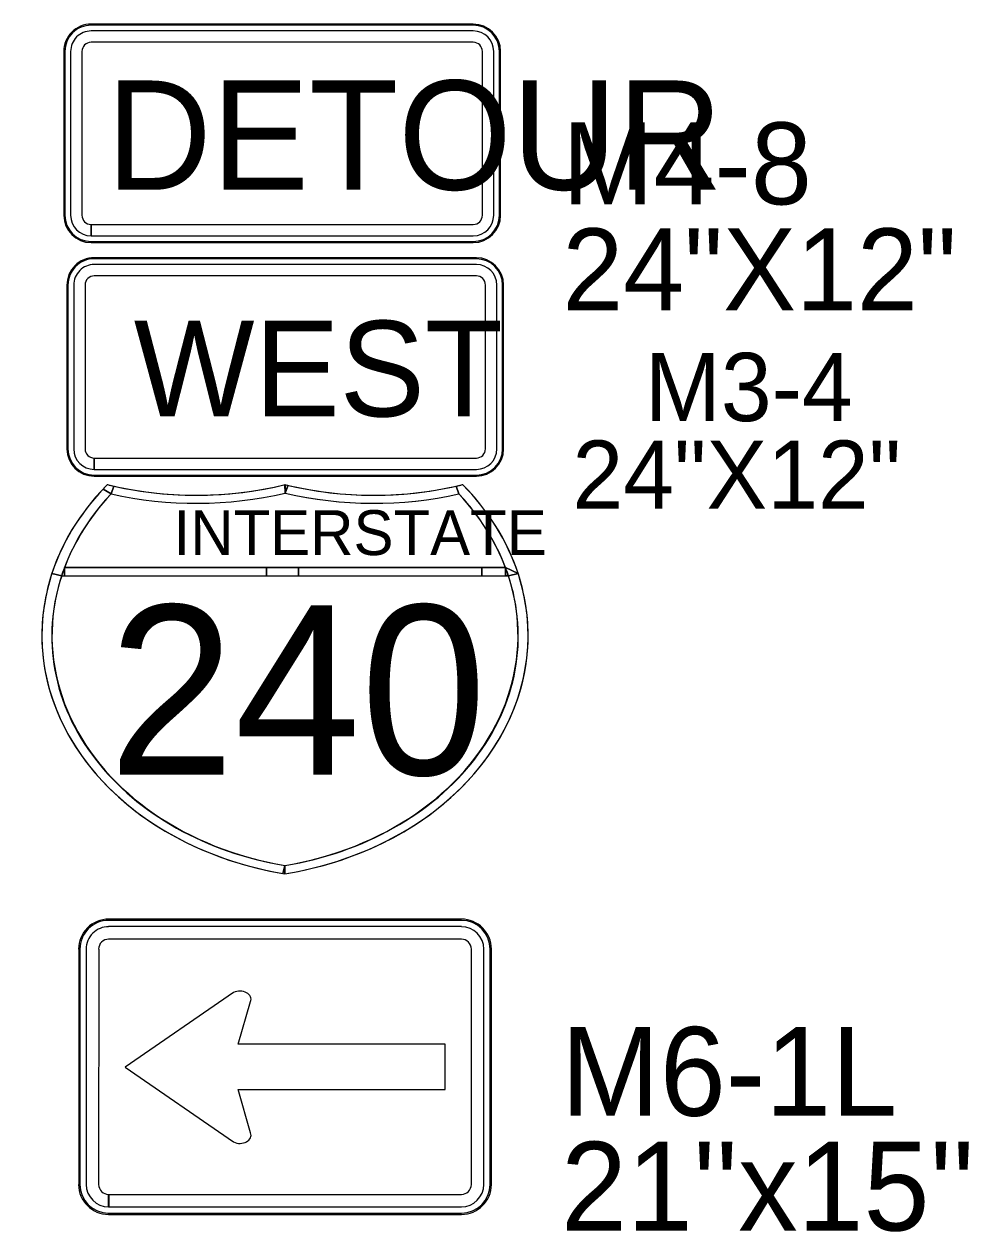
# Model space of a CAD drawing. Extents: x 886234 to 968767, y 455416 to 684046.
# Drawn here: x 908054 to 909092, y 471401 to 472728 of the extents above; entities that cross this region are included whole.
import ezdxf

# ---------------------------------------------------------------- set-up
doc = ezdxf.new("R2010")
doc.units = 0
for name, color, linetype in [('TC DEV SIGN BLACK 239', 7, 'Continuous'), ('TC DEV SIGN BLACK ZERO', 7, 'Continuous'), ('TC DEV SIGN ORANGE', 7, 'Continuous'), ('TC DEV SIGN WHITE', 7, 'Continuous'), ('TC LABEL TEXT', 7, 'Continuous')]:
    doc.layers.add(name, color=color, linetype=linetype)

msp = doc.modelspace()

# ---------------------------------------------------------------- linework, layer by layer
at = {"layer": 'TC DEV SIGN BLACK 239'}
for p, q in [((908551, 472463.9), (908131, 472463.9)), ((908108.5, 472441.4), (908108.5, 472261.4)), ((908121, 472441.4), (908121, 472261.4)), ((908551, 472451.4), (908131, 472451.4)), ((908561, 472261.4), (908561, 472441.4)), ((908573.5, 472261.4), (908573.5, 472441.4)), ((908131, 472238.9), (908131, 472251.4)), ((908131.1, 472251.4), (908551, 472251.4)), ((908131.1, 472251.4), (908131.1, 472238.9)), ((908131.1, 472238.9), (908551, 472238.9)), ((908534.5, 471736.7), (908146.9, 471736.7)), ((908122.2, 471711.9), (908122.2, 471453.5)), ((908136, 471711.9), (908135.9, 471453.5)), ((908534.5, 471722.9), (908146.9, 471722.9)), ((908545.5, 471453.5), (908545.5, 471711.9)), ((908559.3, 471453.5), (908559.3, 471711.9)), ((908284.2, 471664.3), (908165, 471582.2)), ((908289.3, 471607.5), (908302.8, 471654.3)), ((908516.7, 471607.5), (908289.3, 471607.5)), ((908516.7, 471557.7), (908516.7, 471607.5)), ((908165, 471582.2), (908284.2, 471500.1)), ((908302.8, 471510.1), (908289.4, 471557.7)), ((908289.4, 471557.7), (908516.7, 471557.7)), ((908146.9, 471428.8), (908146.9, 471442.5)), ((908147.1, 471442.5), (908534.5, 471442.5)), ((908147.1, 471442.5), (908147.1, 471428.8)), ((908147.1, 471428.8), (908534.5, 471428.8))]:
    msp.add_line(p, q, dxfattribs=at)
for centre, major_axis, ratio, start_param, end_param in [((908131, 472441.4), (22.5, 0), 0.999865, 1.570796, 3.141593), ((908551, 472441.4), (22.5, 0), 0.999865, 0, 1.570796), ((908131, 472441.4), (10, 0), 0.999865, 1.570796, 3.141593), ((908551, 472441.4), (10, 0), 0.999865, 0, 1.570796), ((908131, 472261.4), (22.5, 0), 0.999865, 3.141593, 4.712389), ((908131, 472261.4), (10, 0), 0.999865, 3.141593, 4.712389), ((908551, 472261.4), (22.5, 0), 0.999865, 4.712389, 6.283185), ((908551, 472261.4), (10, 0), 0.999865, 4.712389, 6.283185), ((908146.9, 471711.9), (24.7, 0), 0.999865, 1.570796, 3.141593), ((908534.5, 471711.9), (24.7, 0), 0.999865, 0, 1.570796), ((908146.9, 471711.9), (11, 0), 0.999865, 1.570796, 3.141593), ((908534.5, 471711.9), (11, 0), 0.999865, 0, 1.570796), ((908291.1, 471657), (-12.3, 0), 0.720018, 2.830616, 5.313575), ((908291.1, 471507.4), (-12.3, 0), 0.720018, 0.969609, 3.452568), ((908146.9, 471453.5), (24.7, 0), 0.999865, 3.141593, 4.712389), ((908146.9, 471453.5), (11, 0), 0.999865, 3.141593, 4.712389), ((908534.5, 471453.5), (24.7, 0), 0.999865, 4.712389, 6.283185), ((908534.5, 471453.5), (11, 0), 0.999865, 4.712389, 6.283185)]:
    msp.add_ellipse(centre, major_axis=major_axis, ratio=ratio, start_param=start_param, end_param=end_param, dxfattribs=at)
at = {"layer": 'TC DEV SIGN BLACK ZERO'}
for p, q in [((908547.6, 472728), (908127.6, 472728)), ((908127.6, 472726.7), (908127.6, 472726.7)), ((908547.6, 472726.7), (908127.6, 472726.7)), ((908547.6, 472720.5), (908127.6, 472720.5)), ((908547.6, 472726.7), (908547.6, 472726.7)), ((908547.6, 472708), (908127.6, 472708)), ((908097.6, 472698), (908097.6, 472518)), ((908098.8, 472698), (908098.8, 472518)), ((908098.8, 472698), (908098.8, 472698)), ((908105.1, 472698), (908105.1, 472518)), ((908117.6, 472698), (908117.6, 472518)), ((908557.6, 472518), (908557.6, 472698)), ((908570.1, 472518), (908570.1, 472698)), ((908576.4, 472698), (908576.4, 472698)), ((908576.4, 472518), (908576.4, 472698)), ((908577.6, 472518), (908577.6, 472698)), ((908098.8, 472518), (908098.8, 472518)), ((908127.6, 472495.5), (908127.6, 472508)), ((908127.7, 472508), (908547.6, 472508)), ((908127.7, 472508), (908127.7, 472495.5)), ((908576.4, 472518), (908576.4, 472518)), ((908127.7, 472495.5), (908547.6, 472495.5)), ((908127.6, 472488), (908127.6, 472489.2)), ((908127.6, 472489.2), (908127.6, 472489.2)), ((908127.6, 472489.2), (908547.6, 472489.2)), ((908127.6, 472489.2), (908127.6, 472488)), ((908127.6, 472488), (908547.6, 472488)), ((908547.6, 472489.2), (908547.6, 472489.2)), ((908551, 472471.4), (908131, 472471.4)), ((908131, 472470.2), (908131, 472470.2)), ((908551, 472470.2), (908131, 472470.2)), ((908551, 472470.2), (908551, 472470.2)), ((908101, 472441.4), (908101, 472261.4)), ((908102.2, 472441.4), (908102.2, 472261.4)), ((908102.2, 472441.4), (908102.2, 472441.4)), ((908579.8, 472441.4), (908579.8, 472441.4)), ((908579.8, 472261.4), (908579.8, 472441.4)), ((908581, 472261.4), (908581, 472441.4)), ((908102.2, 472261.4), (908102.2, 472261.4)), ((908579.8, 472261.4), (908579.8, 472261.4)), ((908131, 472231.4), (908131, 472232.7)), ((908131, 472232.7), (908131, 472232.7)), ((908131, 472232.7), (908551, 472232.7)), ((908131, 472232.7), (908131, 472231.4)), ((908131, 472231.4), (908551, 472231.4)), ((908551, 472232.7), (908551, 472232.7)), ((908149.7, 472211.9), (908152.7, 472220.5)), ((908341, 472212.9), (908340.7, 472222.2)), ((908341, 472213.5), (908340.7, 472222.2)), ((908528.8, 472220.5), (908531.8, 472211.9)), ((908098.4, 472131), (908583.1, 472131)), ((908320.3, 472131), (908098.4, 472131)), ((908355.5, 472131), (908320.3, 472131)), ((908556.9, 472131), (908355.5, 472131)), ((908583.1, 472131), (908556.9, 472131)), ((908597, 472124.4), (908583.1, 472131)), ((908586, 472122.7), (908583.1, 472122.1)), ((908095.3, 472122.1), (908586.2, 472122.1)), ((908095.3, 472122.1), (908098.4, 472122.1)), ((908098.4, 472122.1), (908320.3, 472122.1)), ((908320.3, 472122.1), (908355.5, 472122.1)), ((908355.5, 472122.1), (908556.9, 472122.1)), ((908556.9, 472122.1), (908583.1, 472122.1)), ((908583.1, 472122.1), (908586.2, 472122.1)), ((908073.6, 472057.8), (908073.6, 472055.1)), ((908607.9, 472055.1), (908607.9, 472057.9)), ((908340.7, 471794.7), (908340.7, 471803.8)), ((908534.5, 471744.9), (908146.9, 471744.9)), ((908146.9, 471743.5), (908146.9, 471743.5)), ((908534.5, 471743.5), (908146.9, 471743.5)), ((908534.5, 471743.5), (908534.5, 471743.5)), ((908114, 471711.9), (908114, 471453.5)), ((908115.3, 471711.9), (908115.3, 471453.5)), ((908115.3, 471711.9), (908115.4, 471711.9)), ((908566.1, 471711.9), (908566.1, 471711.9)), ((908566.1, 471453.5), (908566.1, 471711.9)), ((908567.5, 471453.5), (908567.5, 471711.9)), ((908115.3, 471453.5), (908115.3, 471453.5)), ((908566.1, 471453.5), (908566.1, 471453.5)), ((908146.9, 471420.6), (908146.9, 471421.9)), ((908146.9, 471421.9), (908146.9, 471421.9)), ((908147, 471421.9), (908534.5, 471421.9)), ((908147, 471421.9), (908147, 471420.6)), ((908147, 471420.6), (908534.5, 471420.6)), ((908534.5, 471421.9), (908534.5, 471421.9))]:
    msp.add_line(p, q, dxfattribs=at)
for points in [[(908140.8, 472217.3), (908149.7, 472211.9)], [(908149.7, 472211.9), (908140.8, 472217.3)], [(908145.6, 472222.2), (908145.5, 472222.2), (908145.5, 472222.2)], [(908152.7, 472220.5), (908149.7, 472211.9)], [(908341, 472222.1), (908341, 472213.5), (908344.2, 472221.4)], [(908344.2, 472221.4), (908341, 472212.9)], [(908531.8, 472211.9), (908528.8, 472220.5)], [(908535.9, 472222.2), (908535.9, 472222.2), (908535.9, 472222.2)], [(908340.7, 472212.9), (908341, 472213.5)], [(908084.5, 472124.4), (908095.3, 472122.1)], [(908095.3, 472122.1), (908084.5, 472124.4)], [(908098.4, 472131), (908098.4, 472122.1)], [(908098.4, 472122.1), (908098.4, 472131)], [(908320.3, 472122.1), (908320.3, 472131)], [(908320.3, 472131), (908320.3, 472122.1)], [(908355.5, 472131), (908355.5, 472122.1)], [(908355.5, 472122.1), (908355.5, 472131)], [(908556.9, 472122.1), (908556.9, 472131)], [(908556.9, 472131), (908556.9, 472122.1)], [(908583.1, 472131), (908597, 472124.4)], [(908583.1, 472122.1), (908583.1, 472131)], [(908583.1, 472131), (908583.1, 472122.1), (908586, 472122.7), (908583.1, 472131)], [(908586.2, 472122.1), (908586, 472122.7)], [(908597, 472124.4), (908586.2, 472122.1)], [(908586.2, 472122.1), (908597, 472124.4)], [(908338.4, 471795.1), (908340.7, 471803.8)], [(908340.7, 471803.8), (908338.4, 471795.1), (908340.7, 471794.7)], [(908340.7, 471803.8), (908340.7, 471794.7)]]:
    msp.add_lwpolyline(points, dxfattribs=at)
for centre, major_axis, ratio, start_param, end_param in [((908127.6, 472698), (30, 0), 0.999865, 1.570796, 3.141593), ((908127.6, 472698), (28.8, 0), 0.999865, 1.570796, 3.141593), ((908127.6, 472698), (22.5, 0), 0.999865, 1.570796, 3.141593), ((908547.6, 472698), (30, 0), 0.999865, 0, 1.570796), ((908547.6, 472698), (28.8, 0), 0.999865, 0, 1.570796), ((908547.6, 472698), (22.5, 0), 0.999865, 0, 1.570796), ((908127.6, 472698), (10, 0), 0.999865, 1.570796, 3.141593), ((908547.6, 472698), (10, 0), 0.999865, 0, 1.570796), ((908127.6, 472518), (30, 0), 0.999865, 3.141593, 4.712389), ((908127.6, 472518), (28.8, 0), 0.999865, 3.141593, 4.712389), ((908127.6, 472518), (22.5, 0), 0.999865, 3.141593, 4.712389), ((908127.6, 472518), (10, 0), 0.999865, 3.141593, 4.712389), ((908547.6, 472518), (22.5, 0), 0.999865, 4.712389, 6.283185), ((908547.6, 472518), (10, 0), 0.999865, 4.712389, 6.283185), ((908547.6, 472518), (30, 0), 0.999865, 4.712389, 6.283185), ((908547.6, 472518), (28.8, 0), 0.999865, 4.712389, 6.283185), ((908131, 472441.4), (30, 0), 0.999865, 1.570796, 3.141593), ((908131, 472441.4), (28.8, 0), 0.999865, 1.570796, 3.141593), ((908551, 472441.4), (30, 0), 0.999865, 0, 1.570796), ((908551, 472441.4), (28.8, 0), 0.999865, 0, 1.570796), ((908131, 472261.4), (30, 0), 0.999865, 3.141593, 4.712389), ((908131, 472261.4), (28.8, 0), 0.999865, 3.141593, 4.712389), ((908551, 472261.4), (30, 0), 0.999865, 4.712389, 6.283185), ((908551, 472261.4), (28.8, 0), 0.999865, 4.712389, 6.283185), ((908407.5, 472056.5), (-334, 0), 0.800002, 5.614188, 7.652625), ((908407.5, 472056.5), (-334, 0), 0.800002, 5.637358, 6.026219), ((908407.5, 472056.5), (-334, 0), 0.800002, 5.614216, 5.637358), ((908243.2, 472477.7), (334, 0), 0.800002, 4.415792, 5.008922), ((908243.2, 472477.7), (334, 0), 0.800002, 4.415856, 4.438209), ((908243.2, 472477.7), (334, 0), 0.800002, 4.438209, 5.008909), ((908438.3, 472477.7), (334, 0), 0.800002, 4.415856, 5.008986), ((908273.9, 472056.5), (334, 0), 0.800002, 4.913746, 6.952183), ((908438.3, 472477.7), (334, 0), 0.800002, 4.416709, 4.426515), ((908438.3, 472477.7), (334, 0), 0.800002, 4.426515, 4.986569), ((908438.3, 472477.7), (334, 0), 0.800002, 4.986569, 5.008922), ((908273.9, 472056.5), (334, 0), 0.800002, 0.256966, 0.66897), ((908407.5, 472056.5), (-322.9, 0), 0.800002, 5.637358, 7.64558), ((908407.5, 472056.5), (-322.9, 0), 0.800002, 5.637358, 6.026219), ((908243.2, 472477.7), (345.1, 0), 0.800002, 4.438209, 4.999074), ((908243.2, 472477.7), (345.1, 0), 0.800002, 4.438209, 4.999074), ((908438.3, 472477.7), (345.1, 0), 0.800002, 4.425704, 4.986569), ((908273.9, 472056.5), (322.9, 0), 0.800002, 4.920791, 6.929013), ((908438.5, 472477.3), (344.6, 0), 0.800002, 4.425686, 4.986568), ((908273.9, 472056.5), (322.9, 0), 0.800002, 0.292795, 0.645828), ((908407.5, 472056.5), (-334, 0), 0.800002, 6.026219, 6.278259), ((908407.5, 472056.5), (-322.9, 0), 0.800002, 5.99039, 6.026219), ((908273.9, 472056.5), (322.9, 0), 0.800002, 0.256966, 0.292795), ((908273.9, 472056.5), (334, 0), 0.800002, 0.005231, 0.256966), ((908406, 472055.7), (-321.6, 0), 0.800002, 6.022151, 7.649781), ((908275.5, 472055.7), (321.6, 0), 0.800002, 4.916934, 6.544356), ((908407.5, 472056.5), (-334, 0), 0.800002, 0.004927, 1.362388), ((908273.9, 472056.5), (334, 0), 0.800002, 4.913748, 6.277955), ((908273.9, 472056.5), (322.9, 0), 0.800002, 4.920791, 4.921138), ((908407.5, 472056.5), (-334, 0), 0.800002, 1.36935, 1.369438), ((908273.9, 472056.5), (334, 0), 0.800002, 4.913747, 4.913748), ((908146.9, 471711.9), (33, 0), 0.999865, 1.570796, 3.141593), ((908146.9, 471711.9), (31.6, 0), 0.999865, 1.570796, 3.141593), ((908534.5, 471711.9), (33, 0), 0.999865, 0, 1.570796), ((908534.5, 471711.9), (31.6, 0), 0.999865, 0, 1.570796), ((908146.9, 471453.5), (33, 0), 0.999865, 3.141593, 4.712389), ((908146.9, 471453.5), (31.6, 0), 0.999865, 3.141593, 4.712389), ((908534.5, 471453.5), (33, 0), 0.999865, 4.712389, 6.283185), ((908534.5, 471453.5), (31.6, 0), 0.999865, 4.712389, 6.283185)]:
    msp.add_ellipse(centre, major_axis=major_axis, ratio=ratio, start_param=start_param, end_param=end_param, dxfattribs=at)
at = {"layer": 'TC DEV SIGN ORANGE'}
for p, q in [((908547.6, 472728), (908127.6, 472728)), ((908097.6, 472698), (908097.6, 472518)), ((908577.6, 472518), (908577.6, 472698)), ((908127.6, 472488), (908547.6, 472488))]:
    msp.add_line(p, q, dxfattribs=at)
for centre, start_param, end_param in [((908127.6, 472698), 1.570796, 3.141593), ((908547.6, 472698), 0, 1.570796), ((908127.6, 472518), 3.141593, 4.712389), ((908547.6, 472518), 4.712389, 6.283185)]:
    msp.add_ellipse(centre, major_axis=(30, 0), ratio=0.999865, start_param=start_param, end_param=end_param, dxfattribs=at)
at = {"layer": 'TC DEV SIGN WHITE'}
for p, q in [((908551, 472471.4), (908131, 472471.4)), ((908101, 472441.4), (908101, 472261.4)), ((908581, 472261.4), (908581, 472441.4)), ((908131, 472231.4), (908551, 472231.4)), ((908534.5, 471744.9), (908146.9, 471744.9)), ((908114, 471711.9), (908114, 471453.5)), ((908567.5, 471453.5), (908567.5, 471711.9)), ((908146.9, 471420.6), (908534.5, 471420.6))]:
    msp.add_line(p, q, dxfattribs=at)
for centre, major_axis, start_param, end_param in [((908131, 472441.4), (30, 0), 1.570796, 3.141593), ((908551, 472441.4), (30, 0), 0, 1.570796), ((908131, 472261.4), (30, 0), 3.141593, 4.712389), ((908551, 472261.4), (30, 0), 4.712389, 6.283185), ((908146.9, 471711.9), (33, 0), 1.570796, 3.141593), ((908534.5, 471711.9), (33, 0), 0, 1.570796), ((908146.9, 471453.5), (33, 0), 3.141593, 4.712389), ((908534.5, 471453.5), (33, 0), 4.712389, 6.283185)]:
    msp.add_ellipse(centre, major_axis=major_axis, ratio=0.999865, start_param=start_param, end_param=end_param, dxfattribs=at)

# ---------------------------------------------------------------- texts
at = {"layer": 'TC DEV SIGN BLACK 239'}
msp.add_text('WEST', height=105, rotation=360, dxfattribs=at).set_placement((908174.6, 472297.1))
at = {"layer": 'TC DEV SIGN BLACK ZERO'}
for s, height, p in [('DETOUR', 120, (908144.2, 472546.1)), ('M4-8', 90, (908645.5, 472530)), ('24"X12"', 90, (908645.5, 472413.6)), ('INTERSTATE', 49.28, (908218.3, 472144.8)), ('240', 186.16, (908146.9, 471903.5)), ('M6-1L', 97.5, (908644, 471528.9)), ("21''x15''", 97.5, (908644, 471402.8))]:
    msp.add_text(s, height=height, rotation=360, dxfattribs=at).set_placement(p)
at = {"layer": 'TC LABEL TEXT'}
for s, p in [('M3-4', (908736.2, 472291.9)), ('24"X12"', (908656.6, 472195.6))]:
    msp.add_text(s, height=75, dxfattribs=at).set_placement(p)

doc.saveas('drawing.dxf')
